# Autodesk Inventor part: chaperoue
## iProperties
Shininess: 21.0
Length Units: 11269
Angle Units: 11279
Time Units: 11290
Mass Units: 11283
Length Display Precision: 3
Angle Display Precision: 2
Compacted: True
Created: 2001-12
Part Number: chaperoue
Material: Par défaut
Document SubType Name: Modélisation
Designer: pichon
Density: 0.0
Volumn: 0.0
Area: 0.0
PropertySet Name: Model Information
Control State: 0
Master: False
Checked Out: False
Author: pichon
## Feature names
1. Révolution1 [Revolution]
2. Extrusion1
3. Symétrie1 [Mirror]
4. Extrusion2
5. Chanfrein1 [Chamfer]
